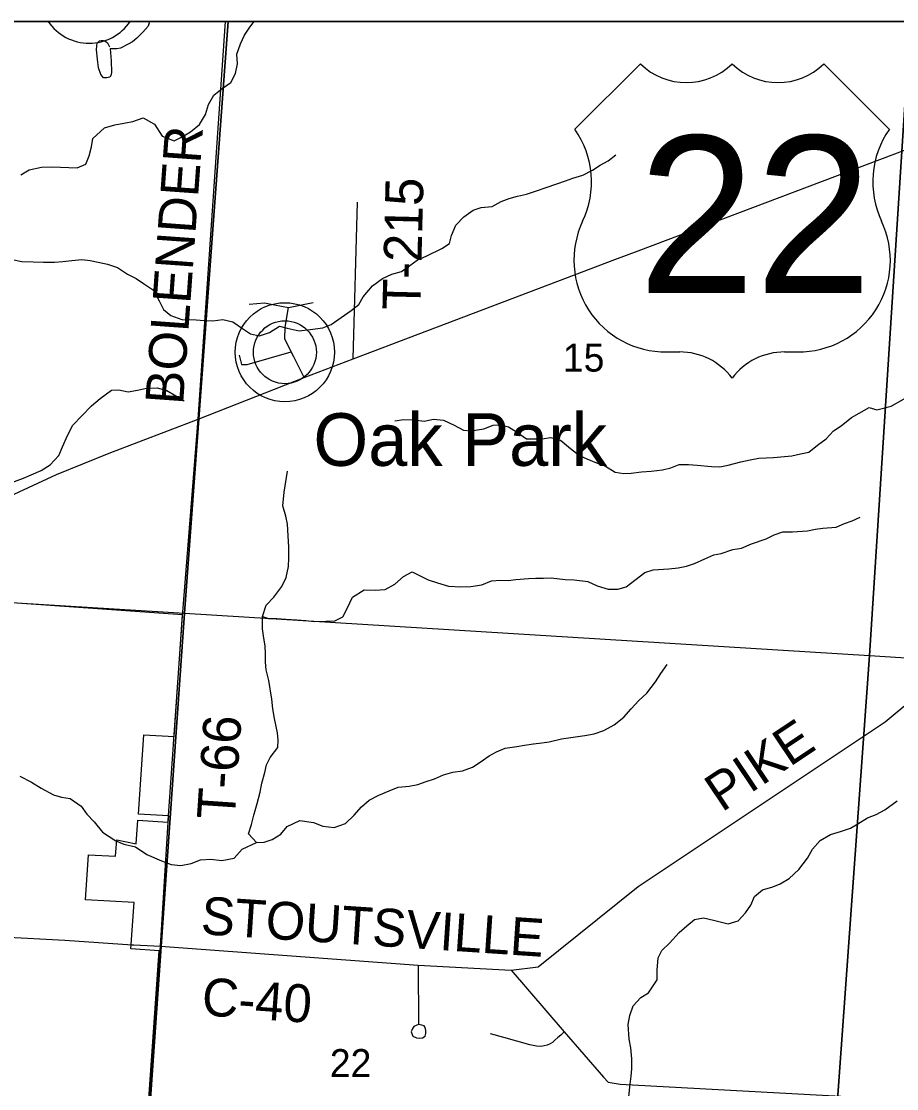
# Model space of a CAD drawing. Extents: x 0 to 42.5, y 0 to 22.
# Drawn here: x 3.889 to 4.545, y 20.099 to 20.9 of the extents above; entities that cross this region are included whole.
import ezdxf

# ---------------------------------------------------------------- set-up
doc = ezdxf.new("R2010")
doc.units = 0
for name, color, linetype in [('Default', 7, 'Continuous'), ('GM_X_County_Road', 7, 'Continuous'), ('GM_X_County_Road_Text', 7, 'Continuous'), ('GM_X_Interchange_Ramps', 7, 'Continuous'), ('GM_X_Minor_River', 7, 'Continuous'), ('GM_X_Section', 7, 'Continuous'), ('GM_X_Section_Text', 7, 'Continuous'), ('GM_X_State_Shield', 7, 'Continuous'), ('GM_X_Township_Road', 7, 'Continuous'), ('GM_X_Township_Road_Text', 7, 'Continuous'), ('GM_X_Unincorporated', 7, 'Continuous'), ('GM_X_Unincorporated_Location', 7, 'Continuous'), ('GM_X_Unincorporated_Text', 7, 'Continuous'), ('GM_X_US_Location', 7, 'Continuous'), ('GM_X_US_Route', 7, 'Continuous'), ('GM_X_US_Shield', 7, 'Continuous'), ('SH_Cut_Line', 7, 'Continuous'), ('SH_Data', 7, 'Continuous')]:
    doc.layers.add(name, color=color, linetype=linetype)

msp = doc.modelspace()

# ---------------------------------------------------------------- linework, layer by layer
at = {"layer": 'Default'}
msp.add_lwpolyline([(3.98148, 20.04863), (3.99204, 20.20267), (3.97093, 20.20401), (3.97338, 20.23896), (3.93688, 20.24087), (3.93924, 20.27469), (3.95948, 20.27363), (3.96034, 20.28591), (3.97497, 20.2828), (3.97626, 20.3006), (3.99873, 20.29912), (3.99903, 20.2991), (3.99932, 20.30398), (3.99907, 20.304), (3.97655, 20.30524), (3.9807, 20.36469), (4.0034, 20.36351), (4.00978, 20.45475), (3.74365, 20.47336)], dxfattribs=at)
at = {"layer": 'GM_X_County_Road'}
msp.add_line((3.97328, 20.20712), (3.99308, 20.20605), dxfattribs=at)
for points in [[(3.99308, 20.20605), (4.18641, 20.19195), (4.25615, 20.1882), (4.27629, 20.19063), (4.35151, 20.25076), (4.53663, 20.37454), (4.57824, 20.40887), (4.60018, 20.41726), (4.78505, 20.40446), (5.0521, 20.38596), (5.43022, 20.36402), (5.51787, 20.35753), (5.54254, 20.35547), (5.55726, 20.35474), (5.56574, 20.3547)], [(3.7457, 20.22016), (3.7601, 20.21934), (3.82766, 20.21554), (3.92139, 20.21048), (3.97179, 20.2072), (3.97328, 20.20712)]]:
    msp.add_lwpolyline(points, dxfattribs=at)
at = {"layer": 'GM_X_Interchange_Ramps'}
msp.add_lwpolyline([(5.48884, 19.405), (5.50057, 19.55251), (5.51061, 19.66936), (5.5156, 19.73605), (5.52526, 19.85376), (5.53536, 19.98472), (5.54606, 20.11658), (5.56474, 20.34561), (5.56563, 20.35496), (5.56586, 20.35729), (5.60252, 20.8068), (5.60957, 20.9), (3.50401, 20.9), (3.49253, 20.65067), (3.48511, 20.52333), (3.47328, 20.34399), (3.47315, 20.34124), (3.46843, 20.23651), (3.46832, 20.23391), (3.43715, 19.68433), (3.40756, 19.23914)], dxfattribs=at)
at = {"layer": 'GM_X_Minor_River'}
for points in [[(3.88831, 20.78474), (3.89478, 20.7885), (3.90388, 20.79053), (3.91203, 20.79086), (3.92453, 20.7904), (3.9306, 20.79017), (3.93706, 20.79278), (3.93975, 20.79904), (3.9413, 20.80587), (3.94248, 20.81214), (3.95105, 20.82006), (3.95902, 20.82229), (3.97249, 20.82487), (3.98009, 20.82767), (3.98859, 20.82286), (3.99441, 20.81389), (4.00348, 20.81041), (4.00937, 20.81342), (4.01565, 20.81699), (4.0225, 20.82264), (4.0269, 20.83003), (4.02922, 20.83761), (4.03306, 20.84462), (4.03953, 20.84952), (4.046, 20.85423), (4.04945, 20.86086), (4.05101, 20.86807), (4.05048, 20.8753), (4.05318, 20.88307), (4.05607, 20.88951), (4.06008, 20.89557), (4.06347, 20.9)], [(3.88186, 20.7213), (3.88905, 20.71993), (3.89777, 20.71949), (3.90553, 20.71925), (3.91368, 20.7192), (3.91994, 20.71973), (3.92657, 20.72064), (3.93416, 20.72135), (3.94041, 20.72055), (3.94646, 20.71937), (3.95346, 20.7178), (3.96103, 20.71528), (3.96839, 20.7103), (3.97481, 20.70702), (3.98047, 20.70338), (3.98783, 20.69839), (3.99214, 20.69038), (3.99532, 20.6839), (4.00098, 20.6793), (4.00911, 20.6764), (4.01991, 20.67595), (4.02597, 20.67553), (4.03241, 20.6753), (4.0398, 20.67639), (4.04737, 20.67444), (4.05473, 20.66945), (4.06077, 20.66561), (4.06739, 20.66405), (4.0748, 20.66647), (4.0824, 20.67118), (4.08808, 20.66981), (4.09716, 20.66785), (4.10532, 20.66875), (4.1148, 20.67002), (4.12125, 20.67245), (4.1361, 20.68299), (4.142, 20.68752), (4.14525, 20.6932), (4.15213, 20.70151), (4.15974, 20.70717), (4.16658, 20.71035), (4.17379, 20.71221), (4.18026, 20.71673), (4.18578, 20.72087), (4.19281, 20.72406), (4.20421, 20.7295), (4.20992, 20.73326), (4.21147, 20.73933), (4.21474, 20.7471), (4.22065, 20.75334), (4.22769, 20.75823), (4.23377, 20.76028), (4.24192, 20.76118), (4.24876, 20.76475), (4.25465, 20.76699), (4.26092, 20.76885), (4.26756, 20.77033), (4.27515, 20.77294), (4.28237, 20.77537), (4.29034, 20.77817), (4.2968, 20.78041), (4.3023, 20.78227), (4.3099, 20.78469), (4.31712, 20.78826), (4.32283, 20.79221), (4.32891, 20.7954), (4.33462, 20.79993)], [(3.88103, 20.55369), (3.89034, 20.55724), (3.89623, 20.55986), (3.90364, 20.56305), (3.91049, 20.56737), (3.91697, 20.57417), (3.91966, 20.58081), (3.92331, 20.58934), (3.92753, 20.5971), (3.9342, 20.60409), (3.94145, 20.61146), (3.94793, 20.61712), (3.9563, 20.62333), (3.9618, 20.62349), (3.9688, 20.62211), (3.976, 20.62321), (3.98265, 20.62487), (3.99061, 20.62501), (3.99798, 20.62307), (4.00459, 20.61903), (4.01082, 20.61519)], [(4.16894, 20.6003), (4.17577, 20.60121), (4.18354, 20.60097), (4.19092, 20.59997), (4.19794, 20.60145), (4.20551, 20.60064), (4.21345, 20.59698), (4.22044, 20.59332), (4.22612, 20.59272), (4.2356, 20.59417), (4.24263, 20.59698), (4.24813, 20.59733), (4.25418, 20.59577), (4.26022, 20.59193), (4.26777, 20.58675), (4.27933, 20.58686), (4.28559, 20.58777), (4.29315, 20.58582), (4.30069, 20.5795), (4.30729, 20.57414), (4.31296, 20.57182), (4.32014, 20.56874), (4.32695, 20.56622), (4.33412, 20.56181), (4.34056, 20.56081), (4.34605, 20.56097), (4.35402, 20.56206), (4.36122, 20.56239), (4.36975, 20.56348), (4.37602, 20.56496), (4.38228, 20.56739), (4.38911, 20.56754), (4.39573, 20.56692), (4.40634, 20.5659), (4.41259, 20.56586), (4.41885, 20.56696), (4.42834, 20.56956), (4.43536, 20.57104), (4.442, 20.57214), (4.45299, 20.57264), (4.46114, 20.57353), (4.46664, 20.57407), (4.47328, 20.57555), (4.47935, 20.57684), (4.48602, 20.58212), (4.4923, 20.58683), (4.49783, 20.59287), (4.50354, 20.59645), (4.51134, 20.60286), (4.51724, 20.60605), (4.52465, 20.61019), (4.53033, 20.60863), (4.54114, 20.61122), (4.55084, 20.61667)], [(4.06508, 20.28398), (4.05925, 20.29029), (4.06137, 20.29731), (4.06312, 20.30451), (4.06564, 20.31305), (4.06796, 20.32159), (4.06914, 20.32842), (4.07147, 20.33639), (4.07264, 20.34208), (4.07551, 20.34777), (4.08105, 20.35514), (4.08147, 20.36065), (4.08093, 20.36617), (4.07872, 20.37682), (4.07744, 20.38424), (4.07654, 20.39147), (4.07435, 20.40555), (4.0725, 20.41335), (4.07197, 20.41906), (4.07182, 20.42514), (4.07166, 20.43141), (4.07056, 20.43731), (4.06966, 20.44416), (4.06971, 20.45347), (4.07242, 20.462), (4.07814, 20.46805), (4.08406, 20.47599), (4.08751, 20.48262), (4.08908, 20.49097), (4.0895, 20.49743), (4.08936, 20.50541), (4.08903, 20.51397), (4.08851, 20.52271), (4.08722, 20.52861), (4.08481, 20.53642), (4.08601, 20.54667), (4.08837, 20.56243)], [(4.06971, 20.45347), (4.07425, 20.45192), (4.08031, 20.45188), (4.08713, 20.45146), (4.09547, 20.45083), (4.10228, 20.45041), (4.10834, 20.44961), (4.11706, 20.44993), (4.12388, 20.45008), (4.12997, 20.45327), (4.13322, 20.45952), (4.13725, 20.46786), (4.146, 20.4735), (4.15415, 20.47326), (4.16154, 20.47378), (4.16896, 20.47773), (4.17543, 20.48339), (4.1819, 20.48696), (4.19399, 20.48099), (4.20079, 20.47866), (4.20912, 20.47633), (4.2184, 20.4757), (4.22598, 20.47584), (4.23414, 20.47731), (4.24135, 20.48011), (4.24818, 20.48083), (4.25386, 20.48041), (4.25955, 20.48114), (4.26922, 20.48202), (4.27471, 20.48218), (4.2804, 20.48214), (4.28627, 20.48248), (4.29669, 20.48109), (4.30332, 20.48105), (4.31373, 20.47965), (4.32072, 20.47656), (4.32885, 20.47385), (4.33605, 20.47399), (4.34232, 20.47566), (4.34898, 20.48075), (4.3564, 20.48641), (4.36267, 20.48846), (4.37442, 20.48914), (4.38143, 20.48986), (4.38769, 20.49115), (4.39377, 20.4932), (4.40137, 20.49676), (4.40821, 20.49976), (4.41371, 20.50067), (4.42244, 20.50366), (4.42889, 20.50476), (4.4363, 20.50794), (4.44732, 20.51167), (4.4534, 20.51467), (4.45985, 20.5171), (4.46705, 20.51686), (4.47843, 20.51774), (4.48431, 20.51903), (4.49, 20.51976), (4.49985, 20.52045), (4.50612, 20.52326), (4.51201, 20.52513), (4.5179, 20.52794)], [(4.36845, 20.41069), (4.37323, 20.4175)], [(3.88766, 20.33377), (3.89634, 20.32915), (3.90371, 20.32454), (3.91296, 20.31973), (3.91901, 20.31798), (3.92545, 20.31699), (3.93375, 20.31105), (3.93788, 20.30513), (3.94334, 20.29939), (3.94955, 20.29175), (3.95974, 20.28503), (3.9656, 20.28253), (3.97449, 20.28057), (3.98298, 20.27481), (3.99394, 20.27018), (4.00113, 20.26747), (4.00851, 20.26667), (4.0161, 20.26814), (4.02313, 20.27075), (4.0309, 20.27127), (4.03904, 20.27046), (4.04834, 20.27211), (4.05444, 20.27892), (4.06508, 20.28398), (4.07096, 20.28413), (4.07703, 20.28618), (4.0835, 20.29013), (4.08827, 20.29599), (4.09758, 20.30049), (4.108, 20.29891), (4.1148, 20.2962), (4.12351, 20.29501), (4.13187, 20.29818), (4.13835, 20.30441), (4.14388, 20.31065), (4.14959, 20.31574), (4.15682, 20.31931), (4.16461, 20.32268), (4.17144, 20.32549), (4.17978, 20.32619), (4.18604, 20.32729), (4.1925, 20.32953), (4.19877, 20.33177), (4.20542, 20.33477), (4.21244, 20.33663), (4.21964, 20.33753), (4.22705, 20.34052), (4.23295, 20.3441), (4.23961, 20.34899), (4.24512, 20.352), (4.25177, 20.35462), (4.2603, 20.35589), (4.26618, 20.357), (4.27282, 20.3579), (4.27908, 20.35862), (4.28477, 20.35935), (4.29387, 20.36157), (4.3026, 20.36284), (4.31151, 20.36412), (4.31834, 20.3654), (4.32556, 20.36783), (4.33335, 20.37215), (4.34077, 20.3778), (4.34612, 20.38423), (4.35184, 20.39046), (4.35794, 20.39594), (4.36443, 20.40445), (4.36845, 20.41069)], [(4.34435, 20.0929), (4.34515, 20.1005), (4.34615, 20.10867), (4.34656, 20.11417), (4.34661, 20.12158), (4.3459, 20.12976), (4.34461, 20.13642), (4.34392, 20.14726), (4.3451, 20.15409), (4.34761, 20.1613), (4.35333, 20.16753), (4.35904, 20.17111), (4.36554, 20.18076), (4.36558, 20.18817), (4.36639, 20.19729), (4.36908, 20.20297), (4.3748, 20.20844), (4.38224, 20.21638), (4.38795, 20.22128), (4.39366, 20.226), (4.40049, 20.22747), (4.40787, 20.22572), (4.41903, 20.22279), (4.42644, 20.22503), (4.43197, 20.23107), (4.43579, 20.23694), (4.43868, 20.24338), (4.44477, 20.24828), (4.45236, 20.25052), (4.45787, 20.25276), (4.46472, 20.2569), (4.47196, 20.2635), (4.47845, 20.27201), (4.48209, 20.27883), (4.48801, 20.28545), (4.49561, 20.28996), (4.5032, 20.29219), (4.51061, 20.29461), (4.51612, 20.298), (4.52335, 20.30251), (4.53, 20.30494), (4.53646, 20.30851), (4.5456, 20.3151)]]:
    msp.add_lwpolyline(points, dxfattribs=at)
at = {"layer": 'GM_X_Section'}
for points in [[(3.48334, 20.48855), (4.01124, 20.45591), (3.97586, 19.95227), (3.4546, 19.98469)], [(4.01124, 20.45591), (4.52494, 20.42409), (4.48862, 19.92064), (3.97586, 19.95227)], [(5.05423, 20.39046), (5.01142, 19.88812), (4.48862, 19.92064), (4.52494, 20.42409)]]:
    msp.add_lwpolyline(points, close=True, dxfattribs=at)
at = {"layer": 'GM_X_State_Shield'}
msp.add_line((3.97052, 20.9), (3.90883, 20.9), dxfattribs=at)
msp.add_arc((3.93967, 20.92079), 0.0372, 213.97855, 326.02145, dxfattribs=at)
at = {"layer": 'GM_X_Township_Road'}
for p, q in [((4.02129, 20.60145), (4.04184, 20.9)), ((4.13777, 20.64673), (4.14084, 20.76439)), ((4.0094, 20.45036), (4.02129, 20.60145))]:
    msp.add_line(p, q, dxfattribs=at)
for points in [[(3.98492, 20.9), (3.98389, 20.89644), (3.9799, 20.89196), (3.97542, 20.88732), (3.97214, 20.88468), (3.96886, 20.88284), (3.96318, 20.87996), (3.96038, 20.87948), (3.95543, 20.8794)], [(3.95543, 20.8794), (3.95615, 20.87028), (3.95647, 20.8618), (3.95607, 20.85981), (3.95513, 20.85816), (3.95255, 20.85764), (3.95047, 20.85772), (3.94959, 20.85853), (3.94839, 20.86013), (3.94671, 20.865), (3.94599, 20.87164), (3.94527, 20.87868), (3.94535, 20.88156), (3.94575, 20.88356), (3.94743, 20.88548), (3.94871, 20.88564), (3.95015, 20.88564), (3.95215, 20.88492), (3.95351, 20.88388), (3.95487, 20.88076)], [(4.0596, 20.68777), (4.07117, 20.68871), (4.07876, 20.68718), (4.0892, 20.68527)], [(4.10086, 20.63285), (4.09318, 20.64821), (4.09124, 20.65209), (4.08635, 20.6619), (4.08673, 20.67064), (4.0892, 20.68527), (4.1076, 20.68904)], [(4.0522, 20.64959), (4.05391, 20.64256), (4.05827, 20.64256), (4.09124, 20.65209)], [(4.00292, 20.35762), (4.00909, 20.44646), (4.0094, 20.45036)], [(3.9992, 20.30393), (4.00265, 20.35372), (4.00292, 20.35762)], [(3.99886, 20.29905), (3.99892, 20.30002), (3.9992, 20.30393)], [(3.99308, 20.20605), (3.99859, 20.29514), (3.99886, 20.29905)], [(3.90165, 19.96292), (3.93361, 20.01156), (3.93857, 20.01626), (3.94542, 20.02152), (3.97489, 20.03817), (3.97871, 20.04251), (3.98159, 20.04837), (3.99308, 20.20605)], [(4.18641, 20.19195), (4.18659, 20.14725), (4.18309, 20.14579), (4.18184, 20.14371), (4.18121, 20.14183), (4.18246, 20.13856), (4.18517, 20.13726), (4.18746, 20.13705), (4.18975, 20.13726), (4.19162, 20.1385), (4.19225, 20.14059), (4.19225, 20.14288), (4.19162, 20.14496), (4.19079, 20.14621), (4.18912, 20.14683), (4.18668, 20.14725)], [(4.25615, 20.1882), (4.296, 20.14191), (4.32531, 20.10786), (4.32888, 20.10404), (4.33796, 20.10264), (4.52648, 20.09239), (4.54463, 20.08826), (4.55577, 20.08418), (4.5961, 20.05672), (4.6248, 20.04265), (4.63589, 20.03529), (4.63998, 20.02916), (4.64842, 20.00815), (4.65349, 20.0041), (4.66608, 19.99615), (4.68652, 19.97994)], [(4.296, 20.14191), (4.29523, 20.14112), (4.29339, 20.13941), (4.29124, 20.13763), (4.289, 20.13551), (4.28708, 20.13386), (4.2854, 20.13288), (4.28326, 20.13188), (4.28083, 20.1313), (4.27829, 20.13094), (4.2752, 20.13108), (4.27019, 20.13205), (4.25064, 20.13752), (4.24056, 20.14039)]]:
    msp.add_lwpolyline(points, dxfattribs=at)
at = {"layer": 'GM_X_Unincorporated'}
for points in [[(4.04384, 20.9), (3.50543, 20.9), (3.48334, 20.48855), (4.01124, 20.45591)], [(4.5553, 20.9), (4.04384, 20.9), (4.01124, 20.45591), (4.52494, 20.42409)], [(5.04506, 20.9), (4.5553, 20.9), (4.52494, 20.42409), (5.05423, 20.39046), (5.09592, 20.89641)]]:
    msp.add_lwpolyline(points, close=True, dxfattribs=at)
for radius in [0.0372, 0.02358]:
    msp.add_circle((4.08646, 20.65172), radius, dxfattribs=at)
at = {"layer": 'GM_X_Unincorporated_Location'}
msp.add_line((4.08646, 20.65172), (4.08646, 20.65172), dxfattribs=at)
at = {"layer": 'GM_X_US_Route'}
for points in [[(4.35153, 20.72788), (4.57558, 20.81251), (4.59837, 20.82114)], [(4.29109, 20.70496), (4.33383, 20.7212), (4.35153, 20.72788)], [(4.02129, 20.60145), (4.10086, 20.63285), (4.13777, 20.64673), (4.29109, 20.70496)], [(3.74212, 20.47632), (3.76859, 20.48941), (3.88009, 20.54365), (3.91506, 20.56001), (3.95465, 20.57598), (4.02129, 20.60145)]]:
    msp.add_lwpolyline(points, dxfattribs=at)
at = {"layer": 'GM_X_US_Shield'}
for p, q in [((4.35311, 20.86812), (4.30398, 20.819)), ((4.53978, 20.819), (4.49066, 20.86812)), ((4.37276, 20.65197), (4.38258, 20.65197)), ((4.46118, 20.65197), (4.47101, 20.65197))]:
    msp.add_line(p, q, dxfattribs=at)
for centre, radius, start, end in [((4.3875, 20.9032), 0.04912, 225.573, 314.427), ((4.45627, 20.9032), 0.04912, 225.573, 314.427), ((4.24765, 20.77955), 0.06877, 334.54712, 35.00093), ((4.59612, 20.77955), 0.06877, 144.99907, 205.45288), ((4.37199, 20.72074), 0.06877, 154.83192, 270.63826), ((4.47177, 20.72074), 0.06877, 269.36174, 25.16808), ((4.38258, 20.60285), 0.04912, 36.8699, 90), ((4.46118, 20.60285), 0.04912, 90, 143.1301)]:
    msp.add_arc(centre, radius, start, end, dxfattribs=at)
at = {"layer": 'SH_Cut_Line'}
msp.add_lwpolyline([(5.48884, 19.405), (5.50057, 19.55251), (5.51061, 19.66936), (5.5156, 19.73605), (5.52526, 19.85376), (5.53536, 19.98472), (5.54606, 20.11658), (5.56474, 20.34561), (5.56563, 20.35496), (5.56586, 20.35729), (5.60252, 20.8068), (5.60957, 20.9), (2.1, 20.9), (2.1, 16.00757)], dxfattribs=at)
at = {"layer": 'SH_Data'}
msp.add_line((2.1, 20.9), (8.9, 20.9), dxfattribs=at)

# ---------------------------------------------------------------- texts
at = {"layer": 'GM_X_County_Road_Text'}
for s, height, rotation, p in [('PIKE', 0.028409, 33.77611, (4.41415, 20.3062)), ('STOUTSVILLE', 0.0284091, 356.19905, (4.0229, 20.21515)), ('C-40', 0.028409, 355.86498, (4.02347, 20.15435))]:
    msp.add_text(s, height=height, rotation=rotation, dxfattribs=at).set_placement(p)
at = {"layer": 'GM_X_Section_Text'}
for s, p in [('15', (4.29495, 20.6372)), ('22', (4.12016, 20.10793))]:
    msp.add_text(s, height=0.020928, rotation=0.00001, dxfattribs=at).set_placement(p)
at = {"layer": 'GM_X_Township_Road_Text'}
for s, rotation, p in [('BOLENDER', 85.86869, (4.01004, 20.61188)), ('T-215', 88.59566, (4.18799, 20.6832)), ('T-66', 86.11874, (4.04874, 20.30042))]:
    msp.add_text(s, height=0.028409, rotation=rotation, dxfattribs=at).set_placement(p)
at = {"layer": 'GM_X_Unincorporated_Text'}
msp.add_text('Oak Park', height=0.039489, rotation=0.00001, dxfattribs=at).set_placement((4.10787, 20.56647))
at = {"layer": 'GM_X_US_Location'}
for s, p in [('/', (4.42492, 20.75124)), ('0', (4.42491, 20.75124))]:
    msp.add_text(s, height=0.0000947, dxfattribs=at).set_placement(p)
msp.add_text('22', height=0.0000947, rotation=0.00001, dxfattribs=at).set_placement((4.40537, 20.73163))
at = {"layer": 'GM_X_US_Shield'}
msp.add_text('22', height=0.117899, dxfattribs=at).set_placement((4.35144, 20.69618))

doc.saveas('drawing.dxf')
